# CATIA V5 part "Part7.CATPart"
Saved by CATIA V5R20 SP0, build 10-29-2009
Part number: 3JT9.5X2X13.5
Revision: ANY
Definition: UNKNOWN
Nomenclature: 3JT9.5X2X13.5
Source: Unknown
Bounding box of the stored display mesh (mm): x -6.581 to 6.581, y -1 to 1, z -6.75 to 6.75
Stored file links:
  C:\Users\Utente\Desktop\IO LAVORO\3D X SITO CF\CUMSA\3D files PW\pw080825\pw080825_injection\Part7.CATPart
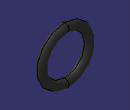
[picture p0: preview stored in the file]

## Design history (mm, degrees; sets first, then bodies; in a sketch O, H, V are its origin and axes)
Body1 "Revolución1" (main body)
  Solid1: solid without history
